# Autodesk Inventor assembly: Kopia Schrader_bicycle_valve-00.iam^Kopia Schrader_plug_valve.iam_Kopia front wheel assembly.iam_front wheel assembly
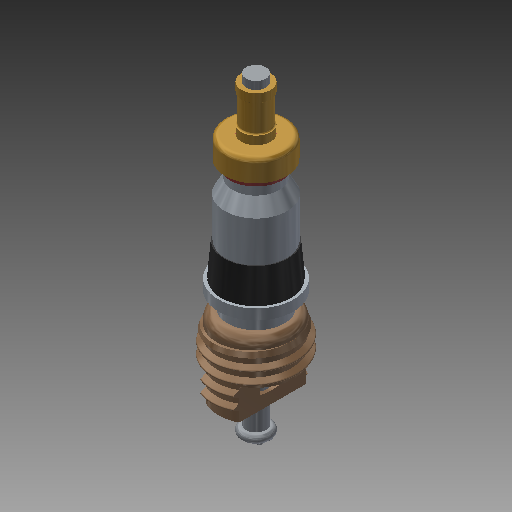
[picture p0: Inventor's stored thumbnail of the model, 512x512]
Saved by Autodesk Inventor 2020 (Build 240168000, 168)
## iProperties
Created: 2017-09
Part Number: Kopia Schrader_bicycle_valve-00.iam^Kopia Schrader_plug_valve.iam_Kopia front wheel assembly.iam_front wheel assembly
Material: Ogólny
Document SubType Name: Assembly
Designer: Tomasz
Sending System: SolidWorks 2017
Last Author: Tomasz
Last Saved: 2017-09-11
Author: Tomasz
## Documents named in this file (8)
- C:\Users\bruno\Documents\1-Cours-2020-21\1STI2D-2020-21\IT\6. Antivol\Inventor-Antivol\INVENTOR 2018_Steel Hardtail B+\Kopia Schrader_bicycle_valve-00.iam^Kopia Schrader_plug_valve.iam_Kopia front wheel assembly.iam_front wheel assembly.iam
- C:\Users\Tomasz\Desktop\Rear Hub Motor Ebike\Kopia Valve_pin.ipt^Kopia Schrader_bicycle_valve-00.iam_Kopia Schrader_plug_valve.iam_Kopia front wheel assembly.iam_front wheel assembly.ipt
- C:\Users\Tomasz\Desktop\Rear Hub Motor Ebike\Kopia Valve_end-00.ipt^Kopia Schrader_bicycle_valve-00.iam_Kopia Schrader_plug_valve.iam_Kopia front wheel assembly.iam_front wheel assembly.ipt
- C:\Users\Tomasz\Desktop\Rear Hub Motor Ebike\Kopia Poppet_seal-00.ipt^Kopia Schrader_bicycle_valve-00.iam_Kopia Schrader_plug_valve.iam_Kopia front wheel assembly.iam_front wheel assembly.ipt
- C:\Users\Tomasz\Desktop\Rear Hub Motor Ebike\Kopia Valve_threads-00.ipt^Kopia Schrader_bicycle_valve-00.iam_Kopia Schrader_plug_valve.iam_Kopia front wheel assembly.iam_front wheel assembly.ipt
- C:\Users\Tomasz\Desktop\Rear Hub Motor Ebike\Kopia Valve_seat-00.ipt^Kopia Schrader_bicycle_valve-00.iam_Kopia Schrader_plug_valve.iam_Kopia front wheel assembly.iam_front wheel assembly.ipt
- C:\Users\Tomasz\Desktop\Rear Hub Motor Ebike\Kopia Vale_outer_seal-00.ipt^Kopia Schrader_bicycle_valve-00.iam_Kopia Schrader_plug_valve.iam_Kopia front wheel assembly.iam_front wheel assembly.ipt
- C:\Users\Tomasz\Desktop\Rear Hub Motor Ebike\Kopia Valve_spring-00.ipt^Kopia Schrader_bicycle_valve-00.iam_Kopia Schrader_plug_valve.iam_Kopia front wheel assembly.iam_front wheel assembly.ipt
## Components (7 placed, 7 different names)
1. Kopia Valve_pin.ipt^Kopia Schrader_bicycle_valve-00.iam_Kopia Schrader_plug_valve.iam_Kopia front wheel assembly.iam_front wheel assembly Solidworks:1
2. Kopia Valve_end-00.ipt^Kopia Schrader_bicycle_valve-00.iam_Kopia Schrader_plug_valve.iam_Kopia front wheel assembly.iam_front wheel assembly Solidworks:1
3. Kopia Poppet_seal-00.ipt^Kopia Schrader_bicycle_valve-00.iam_Kopia Schrader_plug_valve.iam_Kopia front wheel assembly.iam_front wheel assembly Solidworks:1
4. Kopia Valve_threads-00.ipt^Kopia Schrader_bicycle_valve-00.iam_Kopia Schrader_plug_valve.iam_Kopia front wheel assembly.iam_front wheel assembly Solidworks:1
5. Kopia Valve_seat-00.ipt^Kopia Schrader_bicycle_valve-00.iam_Kopia Schrader_plug_valve.iam_Kopia front wheel assembly.iam_front wheel assembly Solidworks:1
6. Kopia Vale_outer_seal-00.ipt^Kopia Schrader_bicycle_valve-00.iam_Kopia Schrader_plug_valve.iam_Kopia front wheel assembly.iam_front wheel assembly Solidworks:1
7. Kopia Valve_spring-00.ipt^Kopia Schrader_bicycle_valve-00.iam_Kopia Schrader_plug_valve.iam_Kopia front wheel assembly.iam_front wheel assembly Solidworks:1
